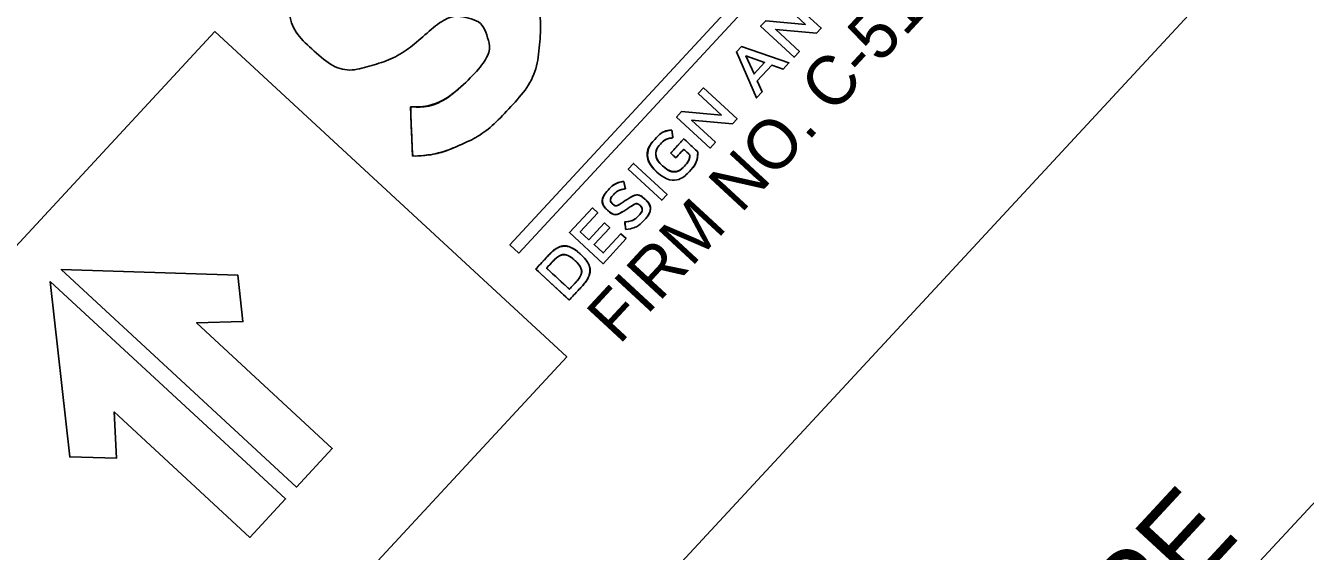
# Model space of a CAD drawing. Extents: x 1766669 to 1770980, y 998119 to 1002502.
# Drawn here: x 1769572.6 to 1769807, y 999842.6 to 999939 of the extents above; entities that cross this region are included whole.
import ezdxf

# ---------------------------------------------------------------- set-up
doc = ezdxf.new("R2010")
doc.units = 0
doc.layers.add('Default Symbol CELL', color=7, linetype='Continuous')

msp = doc.modelspace()

# ---------------------------------------------------------------- linework, layer by layer
at = {"layer": 'Default Symbol CELL'}
for p, q in [((1769610.25, 999751.61), (1770028.19, 1000202.97)), ((1769643.13, 999924.16), (1769643.49, 999915.1)), ((1769691.18, 999918.46), (1769691, 999919.89)), ((1769688.24, 999912.21), (1769688.25, 999912.19)), ((1769689.28, 999913.34), (1769689.26, 999913.35)), ((1769682.47, 999909.13), (1769682.19, 999910.46)), ((1769686.07, 999907.21), (1769686.05, 999907.23)), ((1769679.2, 999905.21), (1769679.22, 999905.19)), ((1769680.12, 999906.36), (1769680.1, 999906.38)), ((1769685.16, 999906.05), (1769685.18, 999906.04)), ((1769682.36, 999903.04), (1769682.53, 999901.68)), ((1769673.22, 999895.98), (1769673.24, 999895.96)), ((1769674.26, 999897.11), (1769674.25, 999897.12)), ((1769667.24, 999699.33), (1769836.77, 999881.92))]:
    msp.add_line(p, q, dxfattribs=at)
for points in [[(1769821.38, 1000068.54), (1769662.96, 999897.34), (1769661.33, 999898.85), (1769819.74, 1000070.05), (1769821.38, 1000068.54)], [(1769819.74, 1000070.05), (1769661.33, 999898.85), (1769662.96, 999897.34), (1769821.38, 1000068.54), (1769819.74, 1000070.05)], [(1769707.24, 999938.91), (1769708.17, 999939.91), (1769715.45, 999939.26), (1769711.2, 999943.19), (1769712.19, 999944.25), (1769718.33, 999938.57), (1769717.49, 999937.67), (1769710, 999938.33), (1769714.36, 999934.29), (1769713.38, 999933.23), (1769707.24, 999938.91)], [(1769713.38, 999933.23), (1769714.36, 999934.29), (1769710, 999938.33), (1769717.49, 999937.67), (1769718.33, 999938.57), (1769712.19, 999944.25), (1769711.2, 999943.19), (1769715.45, 999939.26), (1769708.17, 999939.91), (1769707.24, 999938.91), (1769713.38, 999933.23)], [(1769607.3, 999937.94), (1769535.79, 999860.66), (1769600.23, 999801.02), (1769671.75, 999878.31), (1769607.3, 999937.94)], [(1769607.3, 999937.94), (1769535.79, 999860.66), (1769600.23, 999801.02), (1769671.75, 999878.31), (1769607.3, 999937.94)], [(1769702.81, 999934.2), (1769703.73, 999935.2), (1769712.41, 999932.18), (1769711.36, 999931.04), (1769709.3, 999931.79), (1769706.62, 999928.89), (1769707.52, 999926.89), (1769706.5, 999925.79), (1769702.81, 999934.2)], [(1769706.5, 999925.79), (1769707.52, 999926.89), (1769706.62, 999928.89), (1769709.3, 999931.79), (1769711.36, 999931.04), (1769712.41, 999932.18), (1769703.73, 999935.2), (1769702.81, 999934.2), (1769706.5, 999925.79)], [(1769707.98, 999932.28), (1769704.54, 999933.49), (1769706.03, 999930.17), (1769707.98, 999932.28)], [(1769706.03, 999930.17), (1769704.54, 999933.49), (1769707.98, 999932.28), (1769706.03, 999930.17)], [(1769691.85, 999922.27), (1769692.77, 999923.27), (1769700.06, 999922.63), (1769695.81, 999926.56), (1769696.79, 999927.62), (1769702.93, 999921.93), (1769702.1, 999921.03), (1769694.6, 999921.69), (1769698.97, 999917.65), (1769697.99, 999916.59), (1769691.85, 999922.27)], [(1769697.99, 999916.59), (1769698.97, 999917.65), (1769694.6, 999921.69), (1769702.1, 999921.03), (1769702.93, 999921.93), (1769696.79, 999927.62), (1769695.81, 999926.56), (1769700.06, 999922.63), (1769692.77, 999923.27), (1769691.85, 999922.27), (1769697.99, 999916.59)], [(1769695.76, 999915.89), (1769693.18, 999918.28), (1769690.77, 999915.67), (1769691.71, 999914.8), (1769693.16, 999916.37), (1769694.31, 999915.3)], [(1769682.99, 999912.69), (1769683.98, 999913.77), (1769690.12, 999908.09), (1769689.13, 999907.01), (1769682.99, 999912.69)], [(1769689.13, 999907.01), (1769690.12, 999908.09), (1769683.98, 999913.77), (1769682.99, 999912.69), (1769689.13, 999907.01)], [(1769672.24, 999901.08), (1769676.44, 999905.62), (1769677.41, 999904.73), (1769674.2, 999901.26), (1769675.79, 999899.78), (1769678.64, 999902.86), (1769679.6, 999901.97), (1769676.76, 999898.89), (1769678.41, 999897.37), (1769681.66, 999900.88), (1769682.62, 999899.98), (1769678.38, 999895.39), (1769672.24, 999901.08)], [(1769678.38, 999895.39), (1769682.62, 999899.98), (1769681.66, 999900.88), (1769678.41, 999897.37), (1769676.76, 999898.89), (1769679.6, 999901.97), (1769678.64, 999902.86), (1769675.79, 999899.78), (1769674.2, 999901.26), (1769677.41, 999904.73), (1769676.44, 999905.62), (1769672.24, 999901.08), (1769678.38, 999895.39)], [(1769668.18, 999896.69), (1769666.06, 999894.41), (1769672.2, 999888.72), (1769674.32, 999891.01)], [(1769673.34, 999891.92), (1769672.22, 999890.71), (1769668.04, 999894.57), (1769669.16, 999895.78)], [(1769611.54, 999893.26), (1769612.45, 999884.78), (1769603.95, 999884.52), (1769628.81, 999861.52), (1769622.27, 999854.45), (1769579.18, 999894.33), (1769611.54, 999893.26)], [(1769577.17, 999892.15), (1769620.26, 999852.28), (1769613.72, 999845.21), (1769588.87, 999868.21), (1769589.27, 999859.72), (1769580.74, 999859.97), (1769577.17, 999892.15)], [(1769577.17, 999892.15), (1769620.26, 999852.28), (1769613.72, 999845.21), (1769588.87, 999868.21), (1769589.27, 999859.72), (1769580.74, 999859.97), (1769577.17, 999892.15)]]:
    msp.add_lwpolyline(points, dxfattribs=at)
msp.add_lwpolyline([(1769579.18, 999894.33), (1769622.27, 999854.45), (1769628.81, 999861.52), (1769603.95, 999884.52), (1769612.45, 999884.78), (1769611.54, 999893.26)], close=True, dxfattribs=at)
for points, degree in [([(1769634.21, 999963.17), (1769636.66, 999964.25), (1769639.4, 999964.85), (1769642.42, 999964.96), (1769642.42, 999964.96), (1769642.78, 999955.9), (1769642.78, 999955.9), (1769639.44, 999956.08), (1769636.47, 999954.76), (1769633.86, 999951.93), (1769631.25, 999949.11), (1769630.25, 999946.69), (1769630.86, 999944.67), (1769631.47, 999942.66), (1769632.61, 999941.6), (1769634.27, 999941.52), (1769635.94, 999941.43), (1769638.32, 999942.58), (1769641.39, 999944.96), (1769644.46, 999947.65), (1769647.95, 999949.44), (1769651.84, 999950.35), (1769655.74, 999951.25), (1769659.49, 999950.03), (1769663.1, 999946.69), (1769665.93, 999944.08), (1769667.16, 999940.53), (1769666.8, 999936.05), (1769666.44, 999931.57), (1769664.67, 999927.6), (1769661.48, 999924.15), (1769658.45, 999920.88), (1769655.45, 999918.58), (1769652.47, 999917.26), (1769649.5, 999915.93), (1769646.51, 999915.22), (1769643.49, 999915.1), (1769643.49, 999915.1), (1769643.13, 999924.16), (1769643.13, 999924.16), (1769646.46, 999923.99), (1769650.03, 999925.63), (1769653.82, 999929.1), (1769656.72, 999932.24), (1769657.86, 999934.81), (1769657.24, 999936.82), (1769656.63, 999938.83), (1769655.29, 999940.06), (1769653.24, 999940.52), (1769651.19, 999940.98), (1769648.56, 999939.79), (1769645.34, 999936.95), (1769642.42, 999934.42), (1769639.16, 999932.63), (1769635.57, 999931.59), (1769631.99, 999930.54), (1769628.47, 999931.62), (1769625.01, 999934.81), (1769621.89, 999937.7), (1769620.62, 999941.36), (1769621.2, 999945.78), (1769621.78, 999950.21), (1769623.37, 999953.83), (1769625.98, 999956.65), (1769629.01, 999959.92), (1769631.75, 999962.1), (1769634.21, 999963.17)], 3), ([(1769634.21, 999963.17), (1769631.75, 999962.1), (1769629.01, 999959.92), (1769625.98, 999956.65), (1769623.37, 999953.83), (1769621.78, 999950.21), (1769621.2, 999945.78), (1769620.62, 999941.36), (1769621.89, 999937.7), (1769625.01, 999934.81), (1769628.47, 999931.62), (1769631.99, 999930.54), (1769635.57, 999931.59), (1769639.16, 999932.63), (1769642.42, 999934.42), (1769645.34, 999936.95), (1769648.56, 999939.79), (1769651.19, 999940.98), (1769653.24, 999940.52), (1769655.29, 999940.06), (1769656.63, 999938.83), (1769657.24, 999936.82), (1769657.86, 999934.81), (1769656.72, 999932.24), (1769653.82, 999929.1), (1769650.03, 999925.63), (1769646.46, 999923.99), (1769643.13, 999924.16)], 3), ([(1769643.49, 999915.1), (1769646.51, 999915.22), (1769649.5, 999915.93), (1769652.47, 999917.26), (1769655.45, 999918.58), (1769658.45, 999920.88), (1769661.48, 999924.15), (1769664.67, 999927.6), (1769666.44, 999931.57), (1769666.8, 999936.05), (1769667.16, 999940.53), (1769665.93, 999944.08), (1769663.1, 999946.69), (1769659.49, 999950.03), (1769655.74, 999951.25), (1769651.84, 999950.35), (1769647.95, 999949.44), (1769644.46, 999947.65), (1769641.39, 999944.96), (1769638.32, 999942.58), (1769635.94, 999941.43), (1769634.27, 999941.52), (1769632.61, 999941.6), (1769631.47, 999942.66), (1769630.86, 999944.67), (1769630.25, 999946.69), (1769631.25, 999949.11), (1769633.86, 999951.93), (1769636.47, 999954.76), (1769639.44, 999956.08), (1769642.78, 999955.9)], 3), ([(1769688.25, 999912.19), (1769688.25, 999912.19), (1769688.24, 999912.21), (1769688.24, 999912.21), (1769686.52, 999913.8), (1769686.28, 999916.46), (1769687.99, 999918.31), (1769688.97, 999919.38), (1769689.88, 999919.76), (1769691, 999919.89), (1769691, 999919.89), (1769691.18, 999918.46), (1769691.18, 999918.46), (1769690.34, 999918.36), (1769689.66, 999918.13), (1769688.94, 999917.35), (1769687.89, 999916.22), (1769688.09, 999914.44), (1769689.26, 999913.35), (1769689.26, 999913.35), (1769689.28, 999913.34), (1769689.28, 999913.34), (1769690.54, 999912.17), (1769692.24, 999912.14), (1769693.4, 999913.39), (1769693.94, 999913.97), (1769694.24, 999914.67), (1769694.31, 999915.3), (1769694.31, 999915.3), (1769693.16, 999916.37), (1769693.16, 999916.37), (1769693.16, 999916.37), (1769691.71, 999914.8), (1769691.71, 999914.8), (1769691.71, 999914.8), (1769690.77, 999915.67), (1769690.77, 999915.67), (1769690.77, 999915.67), (1769693.18, 999918.28), (1769693.18, 999918.28), (1769693.18, 999918.28), (1769695.76, 999915.89), (1769695.76, 999915.89), (1769695.72, 999914.81), (1769695.36, 999913.54), (1769694.35, 999912.45), (1769692.58, 999910.53), (1769690.04, 999910.54), (1769688.25, 999912.19)], 3), ([(1769691, 999919.89), (1769689.88, 999919.76), (1769688.97, 999919.38), (1769687.99, 999918.31), (1769686.28, 999916.46), (1769686.52, 999913.8), (1769688.24, 999912.21)], 3), ([(1769689.26, 999913.35), (1769688.09, 999914.44), (1769687.89, 999916.22), (1769688.94, 999917.35), (1769689.66, 999918.13), (1769690.34, 999918.36), (1769691.18, 999918.46)], 3), ([(1769688.25, 999912.19), (1769690.04, 999910.54), (1769692.58, 999910.53), (1769694.35, 999912.45), (1769695.36, 999913.54), (1769695.72, 999914.81), (1769695.76, 999915.89)], 3), ([(1769694.31, 999915.3), (1769694.24, 999914.67), (1769693.94, 999913.97), (1769693.4, 999913.39), (1769692.24, 999912.14), (1769690.54, 999912.17), (1769689.28, 999913.34)], 3), ([(1769682.19, 999910.46), (1769681.11, 999910.3), (1769680.19, 999909.84), (1769679.36, 999908.95), (1769678.23, 999907.73), (1769678.15, 999906.18), (1769679.2, 999905.21)], 3), ([(1769682.53, 999901.68), (1769682.53, 999901.68), (1769682.36, 999903.04), (1769682.36, 999903.04), (1769683.41, 999903.16), (1769684.25, 999903.48), (1769684.95, 999904.24), (1769685.56, 999904.9), (1769685.64, 999905.61), (1769685.18, 999906.04), (1769685.18, 999906.04), (1769685.16, 999906.05), (1769685.16, 999906.05), (1769684.72, 999906.46), (1769684.26, 999906.43), (1769682.94, 999905.54), (1769681.42, 999904.53), (1769680.35, 999904.15), (1769679.22, 999905.19), (1769679.22, 999905.19), (1769679.2, 999905.21), (1769679.2, 999905.21), (1769678.15, 999906.18), (1769678.23, 999907.73), (1769679.36, 999908.95), (1769680.19, 999909.84), (1769681.11, 999910.3), (1769682.19, 999910.46), (1769682.19, 999910.46), (1769682.47, 999909.13), (1769682.47, 999909.13), (1769681.55, 999908.96), (1769680.82, 999908.61), (1769680.3, 999908.05), (1769679.72, 999907.42), (1769679.7, 999906.75), (1769680.1, 999906.38), (1769680.1, 999906.38), (1769680.12, 999906.36), (1769680.12, 999906.36), (1769680.59, 999905.92), (1769681.06, 999906.01), (1769682.44, 999906.93), (1769683.95, 999907.93), (1769685.04, 999908.17), (1769686.05, 999907.23), (1769686.05, 999907.23), (1769686.07, 999907.21), (1769686.07, 999907.21), (1769687.22, 999906.15), (1769687.07, 999904.61), (1769685.88, 999903.33), (1769685.01, 999902.39), (1769683.87, 999901.8), (1769682.53, 999901.68)], 3), ([(1769680.1, 999906.38), (1769679.7, 999906.75), (1769679.72, 999907.42), (1769680.3, 999908.05), (1769680.82, 999908.61), (1769681.55, 999908.96), (1769682.47, 999909.13)], 3), ([(1769686.05, 999907.23), (1769685.04, 999908.17), (1769683.95, 999907.93), (1769682.44, 999906.93), (1769681.06, 999906.01), (1769680.59, 999905.92), (1769680.12, 999906.36)], 3), ([(1769682.53, 999901.68), (1769683.87, 999901.8), (1769685.01, 999902.39), (1769685.88, 999903.33), (1769687.07, 999904.61), (1769687.22, 999906.15), (1769686.07, 999907.21)], 3), ([(1769679.22, 999905.19), (1769680.35, 999904.15), (1769681.42, 999904.53), (1769682.94, 999905.54), (1769684.26, 999906.43), (1769684.72, 999906.46), (1769685.16, 999906.05)], 3), ([(1769685.18, 999906.04), (1769685.64, 999905.61), (1769685.56, 999904.9), (1769684.95, 999904.24), (1769684.25, 999903.48), (1769683.41, 999903.16), (1769682.36, 999903.04)], 3), ([(1769666.06, 999894.41), (1769666.06, 999894.41), (1769668.18, 999896.69), (1769668.18, 999896.69), (1769669.96, 999898.62), (1769672.52, 999898.72), (1769674.25, 999897.12), (1769674.25, 999897.12), (1769674.26, 999897.11), (1769674.26, 999897.11), (1769675.99, 999895.51), (1769676.1, 999892.94), (1769674.32, 999891.01), (1769674.32, 999891.01), (1769672.2, 999888.72), (1769672.2, 999888.72), (1769672.2, 999888.72), (1769666.06, 999894.41), (1769666.06, 999894.41)], 3), ([(1769674.25, 999897.12), (1769672.52, 999898.72), (1769669.96, 999898.62), (1769668.18, 999896.69)], 2), ([(1769668.04, 999894.57), (1769668.04, 999894.57), (1769672.22, 999890.71), (1769672.22, 999890.71), (1769672.22, 999890.71), (1769673.34, 999891.92), (1769673.34, 999891.92), (1769674.53, 999893.21), (1769674.44, 999894.85), (1769673.24, 999895.96), (1769673.24, 999895.96), (1769673.22, 999895.98), (1769673.22, 999895.98), (1769672.02, 999897.09), (1769670.35, 999897.07), (1769669.16, 999895.78), (1769669.16, 999895.78), (1769668.04, 999894.57), (1769668.04, 999894.57)], 3), ([(1769669.16, 999895.78), (1769670.35, 999897.07), (1769672.02, 999897.09), (1769673.22, 999895.98)], 2), ([(1769673.24, 999895.96), (1769674.44, 999894.85), (1769674.53, 999893.21), (1769673.34, 999891.92)], 2), ([(1769674.32, 999891.01), (1769676.1, 999892.94), (1769675.99, 999895.51), (1769674.26, 999897.11)], 2)]:
    msp.add_open_spline(points, degree=degree, dxfattribs=at)

# ---------------------------------------------------------------- texts
for s, height, rotation, p in [('FIRM NO. C-5176', 9.0043, 47.2214, (1769681.36, 999880.38)), ('SPENCER MERRITT, PE', 15.2403, 47.237, (1769696.93, 999684.32)), ('FAITH JAHNKE, PE', 15.2403, 47.237, (1769670.6, 999710.57))]:
    msp.add_text(s, height=height, rotation=rotation, dxfattribs=at).set_placement(p)

doc.saveas('drawing.dxf')
